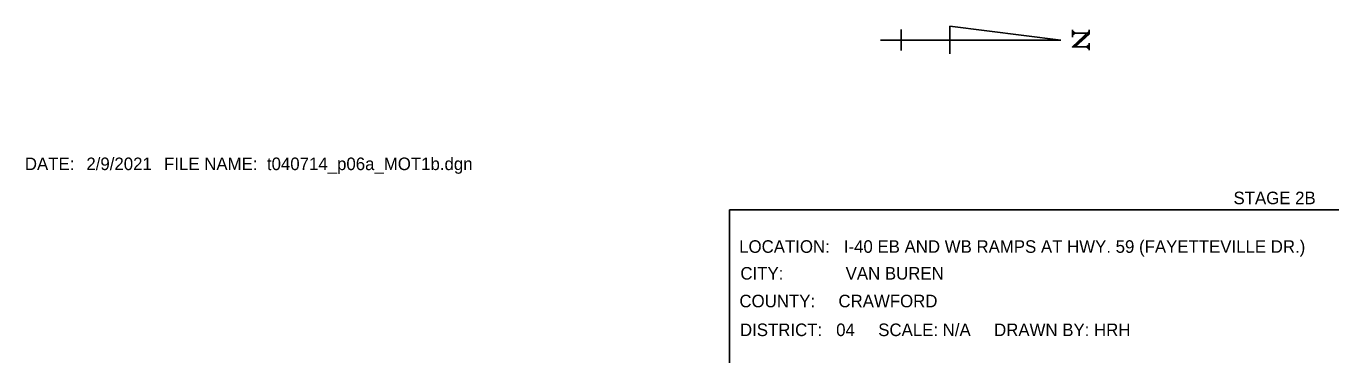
# Model space of a CAD drawing. Extents: x -218554 to 420114, y -565956 to -483460.
# Drawn here: x 419675.3 to 420113.7, y -565956.2 to -565843.6 of the extents above; entities that cross this region are included whole.
import ezdxf

# ---------------------------------------------------------------- set-up
doc = ezdxf.new("R2010")
doc.units = 0
for name, color, linetype in [('Level 1', 7, 'Continuous'), ('Level 10', 7, 'Continuous'), ('Level 57', 7, 'Continuous')]:
    doc.layers.add(name, color=color, linetype=linetype)

msp = doc.modelspace()

# ---------------------------------------------------------------- linework, layer by layer
at = {"layer": 'Level 1'}
for p, q in [((419967.56, -565848.23), (419967.56, -565844.75)), ((419967.56, -565844.75), (419967.56, -565851.71)), ((419983.8, -565843.6), (419983.79, -565852.87)), ((420020.9, -565848.24), (419983.8, -565843.6)), ((419960.61, -565848.23), (420020.9, -565848.24)), ((419960.61, -565848.23), (419974.52, -565848.23)), ((419960.61, -565848.23), (419967.56, -565848.23)), ((420020.9, -565848.24), (419974.52, -565848.23))]:
    msp.add_line(p, q, dxfattribs=at)
for points in [[(420024.77, -565844.84), (420024.77, -565847.25)], [(420030.4, -565845.28), (420024.77, -565850.54), (420029.45, -565850.54), (420030.39, -565851.2)], [(420029.66, -565845.94), (420025.72, -565845.94), (420024.77, -565845.28)], [(420025.72, -565845.94), (420024.77, -565846.23)], [(420024.77, -565846.38), (420025.72, -565845.94), (420024.77, -565846.52)], [(420030.4, -565845.79), (420025.28, -565850.54)], [(420030.4, -565846.01), (420025.58, -565850.54)], [(420030.4, -565844.84), (420030.4, -565846.23), (420025.72, -565850.54)], [(420030.4, -565849.88), (420029.45, -565850.54), (420030.4, -565850.83)], [(420029.45, -565850.54), (420030.39, -565850.98)], [(420030.39, -565849.23), (420030.4, -565851.64)]]:
    msp.add_lwpolyline(points, dxfattribs=at)
at = {"layer": 'Level 57'}
for points in [[(419910.15, -565904.98), (419910.15, -565956.19)], [(420113.73, -565904.98), (419910.15, -565904.98)]]:
    msp.add_lwpolyline(points, dxfattribs=at)

# ---------------------------------------------------------------- texts
at = {"layer": 'Level 10'}
for s, p in [('DATE:  ', (419674.8, -565891.73)), ('2/9/2021', (419695.35, -565891.73)), ('  FILE NAME: ', (419718.18, -565891.73)), ('t040714_p06a_MOT1b.dgn', (419755.67, -565891.73)), ('STAGE 2B', (420078.57, -565903.14)), ('LOCATION:   I-40 EB AND WB RAMPS AT HWY. 59 (FAYETTEVILLE DR.)', (419913.44, -565919.4)), ('CITY:', (419913.84, -565928.36)), (' VAN BUREN', (419947.44, -565928.36)), ('COUNTY:     CRAWFORD', (419913.52, -565937.63)), ('DISTRICT:   04     SCALE: N/A     DRAWN BY: HRH', (419913.7, -565947.26))]:
    msp.add_text(s, height=4.2, rotation=360, dxfattribs=at).set_placement(p)

doc.saveas('drawing.dxf')
